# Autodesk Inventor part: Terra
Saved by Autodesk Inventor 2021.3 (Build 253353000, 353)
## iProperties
Created: 2022-09
Part Number: Terra
Material: Generic
Document SubType Name: Modeling
Designer: Administrator
Density: 1 g/cm^3
Appearance: Default
Title: Terra v3
Author: Administrator
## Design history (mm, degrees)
feature "Terra_" [Body]
feature "Socket Body" [Body]
feature "Shade Ring" [Body]
feature "Shade Ring +Collar" [Body]
feature "Socket" [Body]
feature "Body1"
feature "Metal Strain Relief" [Body]
feature "Fabric Cord (1)" [Body]
feature "Stem (Threaded)" [Body]
feature "Cap (Threaded)" [Body]
feature "5M Set Screw" [Body]
feature "G30-Bulb" [Body]
body "Solid1"
body "Solid2"
body "Solid3"
body "Solid4"
body "Solid5"
body "Solid6"
body "Solid7"
body "Solid8"
body "Solid9"
body "Solid10"
body "Solid11"
body "Solid12"
